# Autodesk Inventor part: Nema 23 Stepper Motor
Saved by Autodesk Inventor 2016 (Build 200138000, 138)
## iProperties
Created: 2016-01
Part Number: Nema 23 Stepper Motor
Material: Generic
Document SubType Name: Modeling
Designer: John
Density: 1 g/cm^3
Appearance: Default
Author: John
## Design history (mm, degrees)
feature "CUT-EXTRUDE7"
body "Solid1"
